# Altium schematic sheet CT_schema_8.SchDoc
size 278 x 170 mm
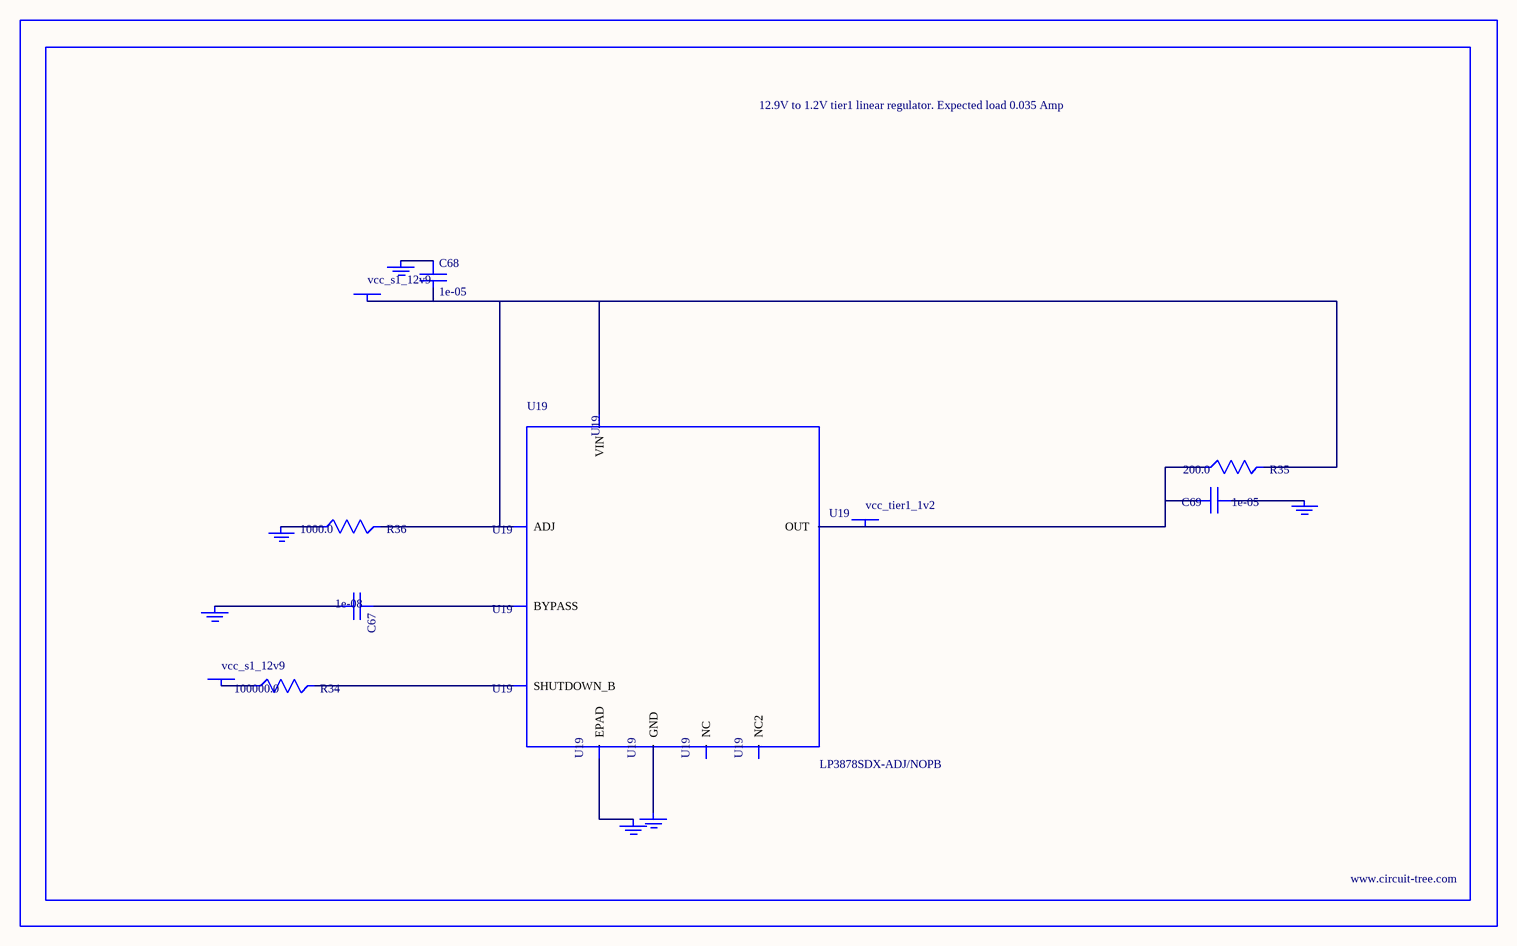
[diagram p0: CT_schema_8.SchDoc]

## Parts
BORDER7  (no value)
C67  1e-08  [C0402]
C68  1e-05  [C1210]
C69  1e-05  [C0805]
GND_INSTANCE_7_0  (no value)
GND_INSTANCE_7_1  (no value)
GND_INSTANCE_7_2  (no value)
GND_INSTANCE_7_3  (no value)
GND_INSTANCE_7_4  (no value)
GND_INSTANCE_7_5  (no value)
POWER_INSTANCE_7_0  vcc_s1_12v9
POWER_INSTANCE_7_1  vcc_s1_12v9
POWER_INSTANCE_7_2  vcc_tier1_1v2
R34  100000.0  [R0603]
R35  200.0  [R0603]
R36  1000.0  [R0603]
U19  LP3878SDX-ADJ/NOPB  [WSON-8]

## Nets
NetC67_1: C67.1 U19.1(BYPASS)
NetC67_2: C67.2 GND_INSTANCE_7_0.0(GND)
NetC68_1: C68.1 GND_INSTANCE_7_1.0(GND)
NetC68_2: C68.2 POWER_INSTANCE_7_0.0(PWR) R35.2 R36.2 U19.4(VIN) U19.6(ADJ)
NetC69_1: C69.1 GND_INSTANCE_7_2.0(GND)
NetC69_2: C69.2 POWER_INSTANCE_7_2.0(PWR) R35.1 U19.5(OUT)
NetGND_INSTANCE_7_3_0: GND_INSTANCE_7_3.0(GND) R36.1
NetGND_INSTANCE_7_4_0: GND_INSTANCE_7_4.0(GND) U19.PAD(EPAD)
NetGND_INSTANCE_7_5_0: GND_INSTANCE_7_5.0(GND) U19.3(GND)
NetPOWER_INSTANCE_7_1_0: POWER_INSTANCE_7_1.0(PWR) R34.1
NetR34_2: R34.2 U19.8(SHUTDOWN_B)

Not connected (* = marked no-connect by the designer): U19 2(NC) 7(NC2)

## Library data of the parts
BORDER7 = BORDER_PAGE7
C67 = C0402C103K3RAC
C68 = C1210C106K5PACTU
C69 = GRM219R60J106ME19D
GND_INSTANCE_7_0-GND_INSTANCE_7_5 = GND
POWER_INSTANCE_7_0-POWER_INSTANCE_7_2 = PWR
R34 = RC0603JR-07100KL
R35 = RC0603JR-07200RL
R36 = RC0603JR-071KL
